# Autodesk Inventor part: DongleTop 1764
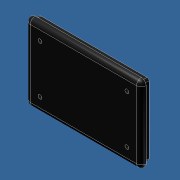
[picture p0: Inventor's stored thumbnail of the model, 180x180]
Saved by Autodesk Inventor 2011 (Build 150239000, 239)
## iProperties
Created: 2010-01
Part Number: DongleTop 1764
Document SubType Name: Modeling
Designer: jgehrig
Density: 1 g/cm^3
Author: jgehrig
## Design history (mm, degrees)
sketch "Sketch1"
  geometry: L1 (-34.141, 54.042)-(42.059, 54.042); L2 (42.059, 54.042)-(42.059, 3.242); L3 (42.059, 3.242)-(-34.141, 3.242); L4 (-34.141, 3.242)-(-34.141, 54.042); 1 further point
  constraints: 8 end point, 2 parallel, 1 horizontal, 1 perpendicular
  dimensions: "d0" = 50.8 distance of L3.end L1.start; "d1" = 76.2 distance of L2.end L3.end
extrude "Extrusion1" new body sketch "Sketch1" distance "d2" = 6.985; taper "d3" = 0 deg
fillet "Fillet1" dims "d4" = 3.175
shell "Shell1" dims "d5" = 4.445
sketch "Sketch2"
  geometry: L1 (-38.884, 3.242)-(30.966, 3.242) reference; L2 (34.141, 6.417)-(34.141, 50.867) reference; L3 (30.966, 54.042)-(-38.884, 54.042) reference; L4 (-42.059, 50.867)-(-42.059, 6.417) reference; L5 (30.966, 5.147)-(-38.884, 5.147); L6 (-40.154, 6.417)-(-40.154, 50.867); L7 (-38.884, 52.137)-(30.966, 52.137); L8 (32.236, 50.867)-(32.236, 6.417); A1 r 3.175 centre (-38.884, 6.417) between (-42.059, 6.417) and (-38.884, 3.242) reference; A2 r 3.175 centre (30.966, 6.417) between (30.966, 3.242) and (34.141, 6.417) reference; A3 r 3.175 centre (30.966, 50.867) between (34.141, 50.867) and (30.966, 54.042) reference; A4 r 3.175 centre (-38.884, 50.867) between (-38.884, 54.042) and (-42.059, 50.867) reference; A5 r 1.27 centre (30.966, 6.417) between (30.966, 5.147) and (32.236, 6.417); A6 r 1.27 centre (-38.884, 6.417) between (-40.154, 6.417) and (-38.884, 5.147); A7 r 1.27 centre (-38.884, 50.867) between (-38.884, 52.137) and (-40.154, 50.867); A8 r 1.27 centre (30.966, 50.867) between (32.236, 50.867) and (30.966, 52.137); 1 further point
  constraints: 8 end point, 8 point on circle, 4 centre point, 7 other
  dimensions: "d6" = 1.905 distance between parallel lines of L1 L5
fillet "Fillet2" dims "d7" = 3.175
extrude "Extrusion2" cut sketch "Sketch2" distance "d8" = 3.81; taper "d9" = 0 deg
sketch "Sketch3"
  geometry: L1 (0, 0)-(60.96, 0) reference; L2 (-3.175, -38.735)-(-3.175, -3.175) reference; L3 (65.405, 2.54)-(-4.445, 2.54) reference; L4 (-5.715, 1.27)-(-5.715, -43.18) reference; L5 (-7.62, -43.18)-(-7.62, 1.27) reference; L6 (-4.445, 4.445)-(65.405, 4.445) reference; C1 r 3.175 at (1.905, -5.08); C2 r 3.175 at (59.055, -5.08); C3 r 3.175 at (1.905, -36.83); C4 r 3.175 at (59.055, -36.83); 1 further point
  constraints: 4 centre point, 1 horizontal, 1 vertical, 6 other
  dimensions: "d10" = 6.35 diameter of C1; "d15" = 57.15 distance of C1.centre C2.centre; "d18" = 31.75 distance of C1.centre C3.centre; "d32" = 9.525 distance from line of L5 C1.centre; "d33" = 9.525 distance from line of L6 C1.centre
extrude "Extrusion3" join sketch "Sketch3" distance "d21" = 4.445; taper "d22" = 0 deg
sketch "Sketch4"
  geometry: L1 (-1.905, 5.08)-(59.055, 5.08) reference; L2 (-5.08, -33.655)-(-5.08, 1.905) reference; L3 (59.055, -36.83)-(-1.905, -36.83) reference; L4 (62.23, 1.905)-(62.23, -33.655) reference; C1 r 3.175 at (57.15, -31.75) reference; C2 r 3.175 at (0, -31.75) reference; C3 r 3.175 at (57.15, 0) reference; C4 r 3.175 at (0, 0) reference; C5 r 1.27 at (0, 0); C6 r 1.27 at (0, -31.75); C7 r 1.27 at (57.15, -31.75); C8 r 1.27 at (57.15, 0); A1 r 3.175 centre (59.055, 1.905) between (62.23, 1.905) and (59.055, 5.08) reference; A2 r 3.175 centre (-1.905, 1.905) between (-1.905, 5.08) and (-5.08, 1.905) reference; A3 r 3.175 centre (-1.905, -33.655) between (-5.08, -33.655) and (-1.905, -36.83) reference; A4 r 3.175 centre (59.055, -33.655) between (59.055, -36.83) and (62.23, -33.655) reference; 1 further point
  constraints: 4 centre point, 4 coincident
  dimensions: "d23" = 2.54 diameter of C5; "d24" = 2.54 diameter of C8; "d25" = 2.54 diameter of C7; "d26" = 2.54 diameter of C6
extrude "Extrusion4" cut sketch "Sketch4" stored distance "d27" = 6.985; taper "d28" = 0 deg
body "Solid1"
node "Projected Loop1"
